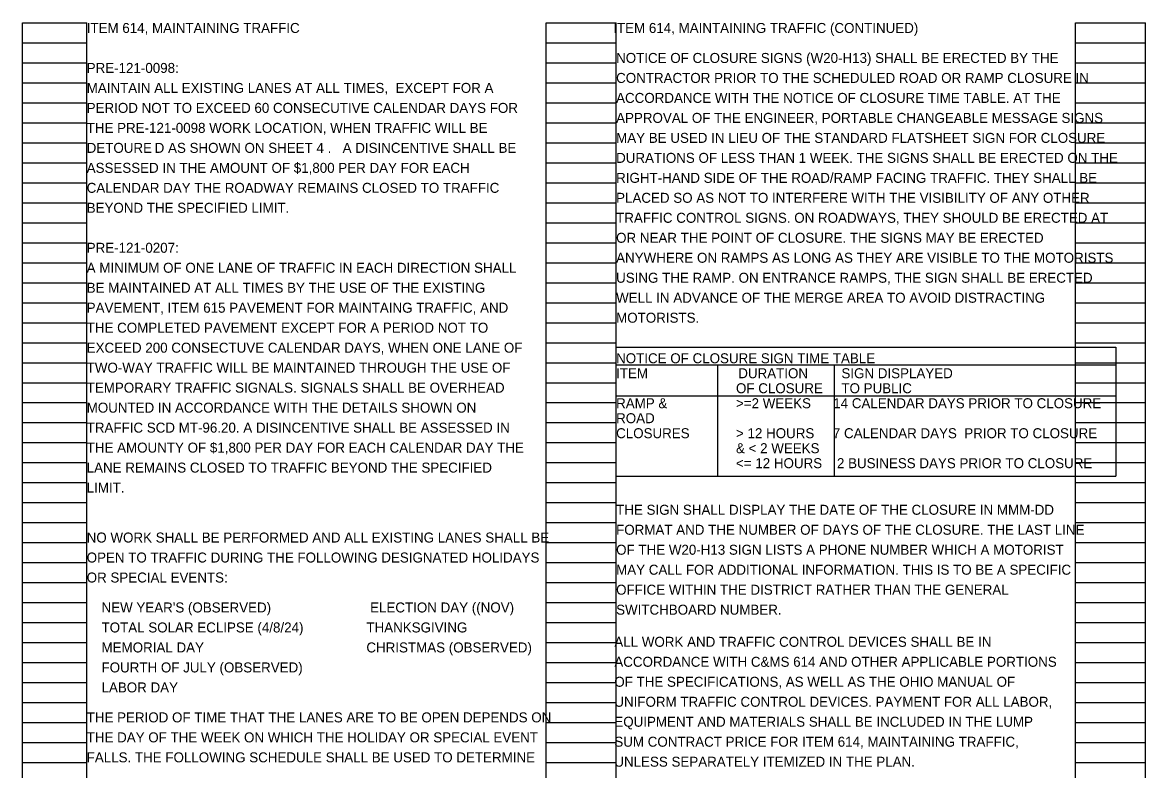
# Model space of a CAD drawing. Extents: x -21.1 to 72.2, y 0 to 46.6.
# Drawn here: x 39.93 to 55.67, y 10.91 to 21.37 of the extents above; entities that cross this region are included whole.
import ezdxf

# ---------------------------------------------------------------- set-up
doc = ezdxf.new("R2010")
doc.units = 0
doc.layers.add('SH_Data', color=7, linetype='Continuous')
doc.layers.add('SH_Text', color=7, linetype='Continuous')

msp = doc.modelspace()

# ---------------------------------------------------------------- linework, layer by layer
at = {"layer": 'SH_Data'}
for p, q in [((39.928, 1.206), (39.928, 21.366)), ((39.928, 21.366), (40.828, 21.366)), ((40.828, 1.206), (40.828, 21.366)), ((47.268, 1.206), (47.268, 21.366)), ((47.268, 21.366), (48.248, 21.366)), ((48.248, 1.206), (48.248, 21.366)), ((54.688, 1.206), (54.688, 21.366)), ((54.688, 21.366), (55.668, 21.366)), ((55.668, 1.206), (55.668, 21.366)), ((39.928, 21.086), (40.828, 21.086)), ((47.268, 21.086), (48.248, 21.086)), ((54.688, 21.086), (55.668, 21.086)), ((39.928, 20.806), (40.828, 20.806)), ((47.268, 20.806), (48.248, 20.806)), ((54.688, 20.806), (55.668, 20.806)), ((39.928, 20.526), (40.828, 20.526)), ((47.268, 20.526), (48.248, 20.526)), ((54.688, 20.526), (55.668, 20.526)), ((39.928, 20.246), (40.828, 20.246)), ((47.268, 20.246), (48.248, 20.246)), ((54.688, 20.246), (55.668, 20.246)), ((39.928, 19.966), (40.828, 19.966)), ((47.268, 19.966), (48.248, 19.966)), ((54.688, 19.966), (55.668, 19.966)), ((39.928, 19.686), (40.828, 19.686)), ((47.268, 19.686), (48.248, 19.686)), ((54.688, 19.686), (55.668, 19.686)), ((39.928, 19.406), (40.828, 19.406)), ((47.268, 19.406), (48.248, 19.406)), ((54.688, 19.406), (55.668, 19.406)), ((39.928, 19.126), (40.828, 19.126)), ((47.268, 19.126), (48.248, 19.126)), ((54.688, 19.126), (55.668, 19.126)), ((39.928, 18.846), (40.828, 18.846)), ((47.268, 18.846), (48.248, 18.846)), ((54.688, 18.846), (55.668, 18.846)), ((39.928, 18.566), (40.828, 18.566)), ((47.268, 18.566), (48.248, 18.566)), ((54.688, 18.566), (55.668, 18.566)), ((39.928, 18.286), (40.828, 18.286)), ((47.268, 18.286), (48.248, 18.286)), ((54.688, 18.286), (55.668, 18.286)), ((39.928, 18.006), (40.828, 18.006)), ((47.268, 18.006), (48.248, 18.006)), ((54.688, 18.006), (55.668, 18.006)), ((39.928, 17.726), (40.828, 17.726)), ((47.268, 17.726), (48.248, 17.726)), ((54.688, 17.726), (55.668, 17.726)), ((39.928, 17.446), (40.828, 17.446)), ((47.268, 17.446), (48.248, 17.446)), ((54.688, 17.446), (55.668, 17.446)), ((39.928, 17.166), (40.828, 17.166)), ((47.268, 17.166), (48.248, 17.166)), ((54.688, 17.166), (55.668, 17.166)), ((39.928, 16.886), (40.828, 16.886)), ((47.268, 16.886), (48.248, 16.886)), ((54.688, 16.886), (55.668, 16.886)), ((39.928, 16.606), (40.828, 16.606)), ((47.268, 16.606), (48.248, 16.606)), ((54.688, 16.606), (55.668, 16.606)), ((39.928, 16.326), (40.828, 16.326)), ((47.268, 16.326), (48.248, 16.326)), ((54.688, 16.326), (55.668, 16.326)), ((39.928, 16.046), (40.828, 16.046)), ((47.268, 16.046), (48.248, 16.046)), ((54.688, 16.046), (55.668, 16.046)), ((39.928, 15.766), (40.828, 15.766)), ((47.268, 15.766), (48.248, 15.766)), ((54.688, 15.766), (55.668, 15.766)), ((39.928, 15.486), (40.828, 15.486)), ((47.268, 15.486), (48.248, 15.486)), ((54.688, 15.486), (55.668, 15.486)), ((39.928, 15.206), (40.828, 15.206)), ((47.268, 15.206), (48.248, 15.206)), ((54.688, 15.206), (55.668, 15.206)), ((39.928, 14.926), (40.828, 14.926)), ((47.268, 14.926), (48.248, 14.926)), ((54.688, 14.926), (55.668, 14.926)), ((39.928, 14.646), (40.828, 14.646)), ((47.268, 14.646), (48.248, 14.646)), ((54.688, 14.646), (55.668, 14.646)), ((39.928, 14.366), (40.828, 14.366)), ((47.268, 14.366), (48.248, 14.366)), ((54.688, 14.366), (55.668, 14.366)), ((39.928, 14.086), (40.828, 14.086)), ((47.268, 14.086), (48.248, 14.086)), ((54.688, 14.086), (55.668, 14.086)), ((39.928, 13.806), (40.828, 13.806)), ((47.268, 13.806), (48.248, 13.806)), ((54.688, 13.806), (55.668, 13.806)), ((39.928, 13.526), (40.828, 13.526)), ((47.268, 13.526), (48.248, 13.526)), ((54.688, 13.526), (55.668, 13.526)), ((39.928, 13.246), (40.828, 13.246)), ((47.268, 13.246), (48.248, 13.246)), ((54.688, 13.246), (55.668, 13.246)), ((39.928, 12.966), (40.828, 12.966)), ((47.268, 12.966), (48.248, 12.966)), ((54.688, 12.966), (55.668, 12.966)), ((39.928, 12.686), (40.828, 12.686)), ((47.268, 12.686), (48.248, 12.686)), ((54.688, 12.686), (55.668, 12.686)), ((39.928, 12.406), (40.828, 12.406)), ((47.268, 12.406), (48.248, 12.406)), ((54.688, 12.406), (55.668, 12.406)), ((39.928, 12.126), (40.828, 12.126)), ((47.268, 12.126), (48.248, 12.126)), ((54.688, 12.126), (55.668, 12.126)), ((39.928, 11.846), (40.828, 11.846)), ((47.268, 11.846), (48.248, 11.846)), ((54.688, 11.846), (55.668, 11.846)), ((39.928, 11.566), (40.828, 11.566)), ((47.268, 11.566), (48.248, 11.566)), ((54.688, 11.566), (55.668, 11.566)), ((39.928, 11.286), (40.828, 11.286)), ((47.268, 11.286), (48.248, 11.286)), ((54.688, 11.286), (55.668, 11.286)), ((39.928, 11.006), (40.828, 11.006)), ((47.268, 11.006), (48.248, 11.006)), ((54.688, 11.006), (55.668, 11.006))]:
    msp.add_line(p, q, dxfattribs=at)
at = {"layer": 'SH_Text'}
for p, q in [((55.252, 16.821), (55.252, 15.015)), ((49.669, 16.57), (49.669, 15.015)), ((51.305, 16.57), (51.305, 15.015)), ((48.248, 14.595), (48.248, 16.402)), ((48.248, 16.143), (55.252, 16.143)), ((48.248, 15.015), (55.252, 15.015))]:
    msp.add_line(p, q, dxfattribs=at)
msp.add_lwpolyline([(55.252, 16.57), (48.248, 16.57), (48.248, 16.822), (55.252, 16.822)], close=True, dxfattribs=at)

# ---------------------------------------------------------------- texts
for s, p in [('ITEM 614, MAINTAINING TRAFFIC', (40.828, 21.226)), ('ITEM 614, MAINTAINING TRAFFIC (CONTINUED)', (48.208, 21.226)), ('NOTICE OF CLOSURE SIGNS (W20-H13) SHALL BE ERECTED BY THE ', (48.248, 20.806)), ('PRE-121-0098:', (40.828, 20.666)), ('CONTRACTOR PRIOR TO THE SCHEDULED ROAD OR RAMP CLOSURE IN ', (48.248, 20.526)), ('MAINTAIN ALL EXISTING LANES AT ALL TIMES,  EXCEPT FOR A ', (40.828, 20.386)), ('ACCORDANCE WITH THE NOTICE OF CLOSURE TIME TABLE. AT THE ', (48.248, 20.246)), ('PERIOD NOT TO EXCEED 60 CONSECUTIVE CALENDAR DAYS FOR ', (40.828, 20.106)), ('APPROVAL OF THE ENGINEER, PORTABLE CHANGEABLE MESSAGE SIGNS ', (48.248, 19.966)), ('THE PRE-121-0098 WORK LOCATION, WHEN TRAFFIC WILL BE ', (40.828, 19.826)), ('DETOURE', (40.828, 19.546)), ('D AS SHOWN ON SHEET 4 . ', (41.781, 19.546)), ('A DISINCENTIVE SHALL BE ', (44.415, 19.546)), ('MAY BE USED IN LIEU OF THE STANDARD FLATSHEET SIGN FOR CLOSURE ', (48.248, 19.686)), ('DURATIONS OF LESS THAN 1 WEEK. THE SIGNS SHALL BE ERECTED ON THE ', (48.248, 19.406)), ('ASSESSED IN THE AMOUNT OF $1,800 PER DAY FOR EACH ', (40.828, 19.266)), ('RIGHT-HAND SIDE OF THE ROAD/RAMP FACING TRAFFIC. THEY SHALL BE ', (48.248, 19.126)), ('CALENDAR DAY THE ROADWAY REMAINS CLOSED TO TRAFFIC ', (40.828, 18.986)), ('PLACED SO AS NOT TO INTERFERE WITH THE VISIBILITY OF ANY OTHER ', (48.248, 18.846)), ('BEYOND THE SPECIFIED LIMIT.', (40.828, 18.706)), ('TRAFFIC CONTROL SIGNS. ON ROADWAYS, THEY SHOULD BE ERECTED AT', (48.248, 18.566)), ('OR NEAR THE POINT OF CLOSURE. THE SIGNS MAY BE ERECTED ', (48.248, 18.286)), ('PRE-121-0207:', (40.828, 18.146)), ('ANYWHERE ON RAMPS AS LONG AS THEY ARE VISIBLE TO THE MOTORISTS ', (48.248, 18.006)), ('A MINIMUM OF ONE LANE OF TRAFFIC IN EACH DIRECTION SHALL ', (40.828, 17.866)), ('USING THE RAMP. ON ENTRANCE RAMPS, THE SIGN SHALL BE ERECTED ', (48.248, 17.726)), ('BE MAINTAINED AT ALL TIMES BY THE USE OF THE EXISTING ', (40.828, 17.586)), ('WELL IN ADVANCE OF THE MERGE AREA TO AVOID DISTRACTING ', (48.248, 17.446)), ('PAVEMENT, ITEM 615 PAVEMENT FOR MAINTAING TRAFFIC, AND ', (40.828, 17.306)), ('THE COMPLETED PAVEMENT EXCEPT FOR A PERIOD NOT TO ', (40.828, 17.026)), ('MOTORISTS.', (48.248, 17.166)), ('EXCEED 200 CONSECTUVE CALENDAR DAYS, WHEN ONE LANE OF ', (40.828, 16.746)), ('NOTICE OF CLOSURE SIGN TIME TABLE', (48.248, 16.598)), ('TWO-WAY TRAFFIC WILL BE MAINTAINED THROUGH THE USE OF ', (40.828, 16.466)), ('ITEM       ', (48.248, 16.388)), ('      DURATION         SIGN DISPLAYED', (49.648, 16.388)), ('TEMPORARY TRAFFIC SIGNALS. SIGNALS SHALL BE OVERHEAD ', (40.828, 16.186)), ('OF CLOSURE     TO PUBLIC', (49.928, 16.178)), ('RAMP &     ', (48.248, 15.968)), ('>=2 WEEKS      14 CALENDAR DAYS PRIOR TO CLOSURE', (49.928, 15.968)), ('MOUNTED IN ACCORDANCE WITH THE DETAILS SHOWN ON ', (40.828, 15.906)), ('ROAD', (48.248, 15.758)), ('TRAFFIC SCD MT-96.20. A DISINCENTIVE SHALL BE ASSESSED IN ', (40.828, 15.626)), ('CLOSURES  ', (48.248, 15.548)), ('> 12 HOURS     7 CALENDAR DAYS  PRIOR TO CLOSURE', (49.928, 15.548)), ('THE AMOUNTY OF $1,800 PER DAY FOR EACH CALENDAR DAY THE ', (40.828, 15.346)), ('& < 2 WEEKS    ', (49.928, 15.338)), ('<= 12 HOURS    2 BUSINESS DAYS PRIOR TO CLOSURE', (49.928, 15.128)), ('LANE REMAINS CLOSED TO TRAFFIC BEYOND THE SPECIFIED ', (40.828, 15.066)), ('LIMIT.', (40.828, 14.786)), ('THE SIGN SHALL DISPLAY THE DATE OF THE CLOSURE IN MMM-DD ', (48.248, 14.475)), ('FORMAT AND THE NUMBER OF DAYS OF THE CLOSURE. THE LAST LINE ', (48.248, 14.195)), ('NO WORK SHALL BE PERFORMED AND ALL EXISTING LANES SHALL BE', (40.828, 14.086)), ('OF THE W20-H13 SIGN LISTS A PHONE NUMBER WHICH A MOTORIST ', (48.248, 13.915)), ('OPEN TO TRAFFIC DURING THE FOLLOWING DESIGNATED HOLIDAYS', (40.828, 13.806)), ('MAY CALL FOR ADDITIONAL INFORMATION. THIS IS TO BE A SPECIFIC ', (48.248, 13.635)), ('OR SPECIAL EVENTS:', (40.828, 13.526)), ('OFFICE WITHIN THE DISTRICT RATHER THAN THE GENERAL ', (48.248, 13.355)), ("    NEW YEAR'S (OBSERVED)          ", (40.828, 13.106)), (' ELECTION DAY ((NOV)', (44.748, 13.106)), ('SWITCHBOARD NUMBER.', (48.248, 13.075)), ('    TOTAL SOLAR ECLIPSE (4/8/24)   ', (40.828, 12.826)), ('THANKSGIVING', (44.748, 12.826)), ('ALL WORK AND TRAFFIC CONTROL DEVICES SHALL BE IN ', (48.223, 12.625)), ('    MEMORIAL DAY                  ', (40.828, 12.546)), ('CHRISTMAS (OBSERVED)', (44.748, 12.546)), ('ACCORDANCE WITH C&MS 614 AND OTHER APPLICABLE PORTIONS ', (48.223, 12.345)), ('    FOURTH OF JULY (OBSERVED)      ', (40.828, 12.266)), ('    LABOR DAY', (40.828, 11.986)), ('OF THE SPECIFICATIONS, AS WELL AS THE OHIO MANUAL OF ', (48.223, 12.065)), ('UNIFORM TRAFFIC CONTROL DEVICES. PAYMENT FOR ALL LABOR, ', (48.223, 11.785)), ('THE PERIOD OF TIME THAT THE LANES ARE TO BE OPEN DEPENDS ON', (40.828, 11.566)), ('EQUIPMENT AND MATERIALS SHALL BE INCLUDED IN THE LUMP ', (48.223, 11.505)), ('THE DAY OF THE WEEK ON WHICH THE HOLIDAY OR SPECIAL EVENT', (40.828, 11.286)), ('SUM CONTRACT PRICE FOR ITEM 614, MAINTAINING TRAFFIC, ', (48.223, 11.225)), ('FALLS. THE FOLLOWING SCHEDULE SHALL BE USED TO DETERMINE', (40.828, 11.006)), ('UNLESS SEPARATELY ITEMIZED IN THE PLAN.', (48.223, 10.945))]:
    msp.add_text(s, height=0.14, dxfattribs=at).set_placement(p)

doc.saveas('drawing.dxf')
